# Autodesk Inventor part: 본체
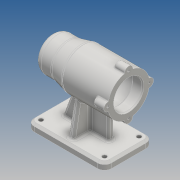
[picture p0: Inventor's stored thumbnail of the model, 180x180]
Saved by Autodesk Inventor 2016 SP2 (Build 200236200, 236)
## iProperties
Created: 2019-07
Part Number: 본체
Material: ABS 플라스틱
Document SubType Name: Modeling
Designer: EZ
Density: 1.06 g/cm^3
Appearance: 매끄러움 - 흰색
Mass: 252.637 g
Surface Area: 656.425 cm^2
Volume: 238.337 cm^3
Author: EZ
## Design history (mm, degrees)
sketch "스케치1"
  geometry: L1 (46, 35)-(-46, 35); L2 (-56, 25)-(-56, -25); L3 (-46, -35)-(46, -35); L4 (56, -25)-(56, 25); L5 (56, 35)-(-56, -35); L6 (-56, 35)-(56, -35); A1 r 10 centre (-46, 25) between (-46, 35) and (-56, 25); A2 r 10 centre (46, 25) between (56, 25) and (46, 35); A3 r 10 centre (46, -25) between (46, -35) and (56, -25); A4 r 10 centre (-46, -25) between (-56, -25) and (-46, -35); 1 further point
  constraints: 12 end point, 8 point on circle, 8 point on line, 8 tangent, 4 centre point, 3 equal radius, 2 midpoint, 2 parallel, 1 horizontal, 1 perpendicular
  dimensions: "d0" = 112 distance of L6.end L5.end; "d1" = 70 distance of L5.end L6.start; "d2" = 10 radius of A1
extrude "돌출1" new body sketch "스케치1" distance "d3" = 10; taper "d4" = 0 deg
sketch "스케치2"
  geometry: L1 (46, 35)-(-46, 35) reference; L2 (-56, 25)-(-56, -25) reference; L3 (-46, -35)-(46, -35) reference; L4 (56, -25)-(56, 25) reference; A1 r 10 centre (-46, 25) between (-46, 35) and (-56, 25) reference; A2 r 10 centre (-46, -25) between (-56, -25) and (-46, -35) reference; A3 r 10 centre (46, -25) between (46, -35) and (56, -25) reference; A4 r 10 centre (46, 25) between (56, 25) and (46, 35) reference; 5 further points
  constraints: 4 coincident
hole "구멍1" sketch "스케치2" at (-46, 25), (-46, -25), (46, -25), (46, 25) diameter "d5" = 6; stored, may be unused: countersink angle "d9" = 90 deg, drill point angle "d11" = 118 deg; dims "d6" = 6, "d7" = 4, "d8" = 2, "d10" = 8
sketch "스케치3"
  geometry: 1 further point
sketch "스케치4"
  geometry: L1 (0, 25)-(-80, 25); C1 r 30 at (-80, 25)
  constraints: 2 end point, 1 centre point, 1 coincident, 1 horizontal
  dimensions: "d12" = 80 distance of L1.start L1.end; "d13" = 60 diameter of C1
extrude "돌출2" join sketch "스케치4" distance "d14" = 67; taper "d15" = 0 deg
sketch "스케치6"
  geometry: C1 r 30 at (0, 0) reference; C2 r 25 at (0, 0); 1 further point
  constraints: 1 centre point, 1 coincident
  dimensions: "d16" = 50 diameter of C2
extrude "돌출3" join sketch "스케치6" distance "d17" = 20; taper "d18" = 0 deg
sketch "스케치7"
  geometry: C1 r 25 at (0, 0) reference; C2 r 25 at (0, 0); 1 further point
  constraints: 1 centre point, 1 coincident
  dimensions: "d19" = 50 diameter of C2
extrude "돌출4" join sketch "스케치7" distance "d20" = 25; taper "d21" = 0 deg
sketch "스케치8"
  geometry: L1 (56, 55)-(56, 105) reference; L2 (11, 105)-(11, 55) reference; L3 (11, 105)-(56, 105) reference; L4 (11, 50)-(11, 110) reference; L5 (-56, 50)-(-56, 110) reference; L6 (11, 105)-(31, 105); L7 (31, 105)-(11, 110); L8 (11, 110)-(11, 105); L9 (56, 80)-(-56, 80); 1 further point
  constraints: 8 end point, 2 midpoint, 1 collinear, 1 point on line
  dimensions: "d22" = 20 distance of L3.start L6.end
revolve "회전1" sketch "스케치8" stored, may be unused: angle "d23" = 90 deg
fillet "모깎기1" dims "d24" = 10
sketch "스케치10"
  geometry: C1 r 30 at (0, 0) reference; C2 r 21 at (0, 0); 1 further point
  constraints: 1 centre point, 1 coincident
  dimensions: "d41" = 42 diameter of C2
extrude "돌출5" cut sketch "스케치10" distance "d42" = 15; taper "d43" = 0 deg
sketch "스케치11"
  geometry: C1 r 21 at (0, 0) reference; C2 r 24 at (0, 0); 1 further point
  constraints: 1 centre point, 1 coincident
  dimensions: "d44" = 48 diameter of C2
extrude "돌출6" cut sketch "스케치11" distance "d45" = 54; taper "d46" = 0 deg
sketch "스케치12"
  geometry: C1 r 24 at (0, 0) reference; C2 r 21 at (0, 0); 1 further point
  constraints: 1 centre point, 1 coincident
  dimensions: "d47" = 42 diameter of C2
extrude "돌출7" cut sketch "스케치12" distance "d48" = 12; taper "d49" = 0 deg
sketch "스케치13"
  geometry: C1 r 25 at (0, 0) reference; C2 r 15 at (0, 0) reference; C3 r 17.5 at (0, 0); 1 further point
  constraints: 1 centre point, 1 coincident
  dimensions: "d50" = 35 diameter of C3
extrude "돌출8" cut sketch "스케치13" distance "d51" = 18; taper "d52" = 0 deg
sketch "스케치14"
  geometry: C1 r 17.5 at (0, 0) reference; C2 r 16 at (0, 0); 1 further point
  constraints: 1 centre point, 1 coincident
  dimensions: "d53" = 32 diameter of C2
extrude "돌출9" cut sketch "스케치14" distance "d54" = 4; taper "d55" = 0 deg
sketch "스케치15"
  geometry: C1 r 16 at (0, 0) reference; C2 r 10.5 at (0, 0); 1 further point
  constraints: 1 centre point, 1 coincident
  dimensions: "d56" = 21 diameter of C2
extrude "돌출10" cut sketch "스케치15" distance "d57" = 3; taper "d58" = 0 deg
sketch "스케치17"
  geometry: L1 (56, 25)-(56, -25) reference; L2 (56, 0)-(31, 0); L3 (0, 0)-(31, 0); L4 (31, 0)-(31, 4); L5 (31, 4)-(0, 4); L6 (0, 0)-(0, 4); L7 (0, 0)-(0, -4); L8 (0, -4)-(31, -4); L9 (31, -4)-(31, 0)
  constraints: 16 end point, 4 perpendicular, 2 horizontal, 1 midpoint, 1 point on line, 1 vertical
  dimensions: "d59" = 25 distance of L2.start L2.end; "d60" = 4 distance of L2.end L4.end; "d61" = 4 distance of L3.start L7.end
extrude "돌출11" join sketch "스케치17" stored distance "d62" = 3; taper "d63" = 0 deg
sketch "스케치18"
  geometry: L1 (0, 10)-(0, 50.268) reference; L2 (-46, 10)-(46, 10) reference; L3 (36, 10)-(20.57, 52.393); L4 (56, 0)-(56, 10) reference; L5 (11, 50)-(31, 55) reference; L6 (36, 10)-(0, 10); 1 further point
  constraints: 4 end point, 2 point on line, 1 collinear
  dimensions: "d64" = 110 deg angle of L2 L3; "d65" = 20 distance from line of L4 L3.start
feature "리브1" sketch "스케치18" dims "d66" = 1, "d67" = 8, "d68" = 0, "d69" = 0, "d70" = 1, "d71" = 1
sketch "스케치19"
  geometry: L1 (-4, 10)-(-4, 52.659) reference; L2 (22, 10)-(28, 10) reference; L3 (35, 10)-(25, 10) reference; L4 (28, 10)-(19.654, 57.334); L5 (35, 0)-(35, 10) reference; L6 (25, 10)-(-25, 10) reference; L7 (28, 10)-(4, 10); A1 r 30 centre (0, 80) between (4, 50.268) and (-4, 50.268) reference; 1 further point
  constraints: 4 end point, 2 point on line, 1 point on circle
  dimensions: "d74" = 100 deg angle of L3 L4; "d75" = 7 distance from line of L5 L4.start
feature "리브2" sketch "스케치19" dims "d76" = 1, "d77" = 8, "d78" = 0, "d79" = 0, "d80" = 1, "d81" = 1
sketch "스케치20"
  geometry: L1 (-4, 10)-(-4, 52.659) reference; L2 (25, 10)-(-25, 10) reference; L3 (-25, 10)-(-35, 10) reference; L4 (-28, 10)-(-19.654, 57.334); L5 (-35, 0)-(-35, 10) reference; L6 (-28, 10)-(-4, 10); A1 r 30 centre (0, 80) between (4, 50.268) and (-4, 50.268) reference; 1 further point
  constraints: 4 end point, 1 collinear, 1 point on circle, 1 point on line
  dimensions: "d82" = 100 deg angle of L3 L4; "d83" = 7 distance from line of L5 L4.start
extrude "돌출12" join sketch "스케치20" stored distance "d84" = 8; taper "d85" = 0 deg
sketch "스케치21"
  geometry: L1 (0, 0)-(-30, 0); L2 (0, 0)-(0, -30); L3 (0, 0)-(30, 0); L4 (0, 0)-(0, 30); C1 r 21 at (0, 0) reference; C2 r 6 at (-30, 0); C3 r 6 at (0, -30); C4 r 6 at (30, 0); C5 r 6 at (0, 30); A1 r 30 centre (0, 0) between (-30, 0) and (0, -30) reference; 1 further point
  constraints: 8 end point, 4 centre point, 4 coincident, 4 point on circle, 1 horizontal, 1 perpendicular, 1 point on line, 1 vertical
  dimensions: "d86" = 12 diameter of C2; "d87" = 12 diameter of C3; "d88" = 12 diameter of C4; "d89" = 12 diameter of C5
extrude "돌출13" join sketch "스케치21" distance "d90" = 16; taper "d91" = 0 deg
sketch "스케치22"
  geometry: A1 r 6 centre (-110, 25) between (-109.4, 30.97) and (-109.4, 19.03) reference; A2 r 6 centre (-80, 55) between (-74.03, 54.4) and (-85.97, 54.4) reference; A3 r 6 centre (-50, 25) between (-50.6, 19.03) and (-50.6, 30.97) reference; A4 r 6 centre (-80, -5) between (-85.97, -4.4) and (-74.03, -4.4) reference; 5 further points
  constraints: 4 coincident
hole "구멍2" sketch "스케치22" at (-80, 55), (-50, 25), (-80, -5), (-110, 25) diameter "d92" = 3.242; stored, may be unused: countersink angle "d96" = 90 deg, drill point angle "d98" = 118 deg; dims "d93" = 8, "d94" = 4, "d95" = 2, "d97" = 11
chamfer "모따기1" distance "d99" = 1; stored, may be unused: second distance "d100" = 2, angle "d101" = 45 deg
chamfer "모따기2" distance "d102" = 1; stored, may be unused: second distance "d103" = 2, angle "d104" = 45 deg
chamfer "모따기3" distance "d105" = 1; stored, may be unused: second distance "d106" = 2, angle "d107" = 45 deg
chamfer "모따기4" distance "d108" = 3; stored, may be unused: second distance "d109" = 2, angle "d110" = 45 deg
fillet "모깎기2" dims "d111" = 3
fillet "모깎기3" dims "d112" = 1
fillet "모깎기5" dims "d114" = 0.3
fillet "모깎기6" dims "d115" = 3
fillet "모깎기7" dims "d119" = 3
fillet "모깎기8" dims "d120" = 3
node "솔리드1"
node "투영된 루프1"
node "투영된 루프3"
node "투영된 루프4"
node "투영된 루프5"
node "투영된 루프6"
node "투영된 루프8"
node "투영된 루프9"
node "투영된 루프10"
node "투영된 루프11"
node "투영된 루프12"
node "투영된 루프13"
node "투영된 루프14"
